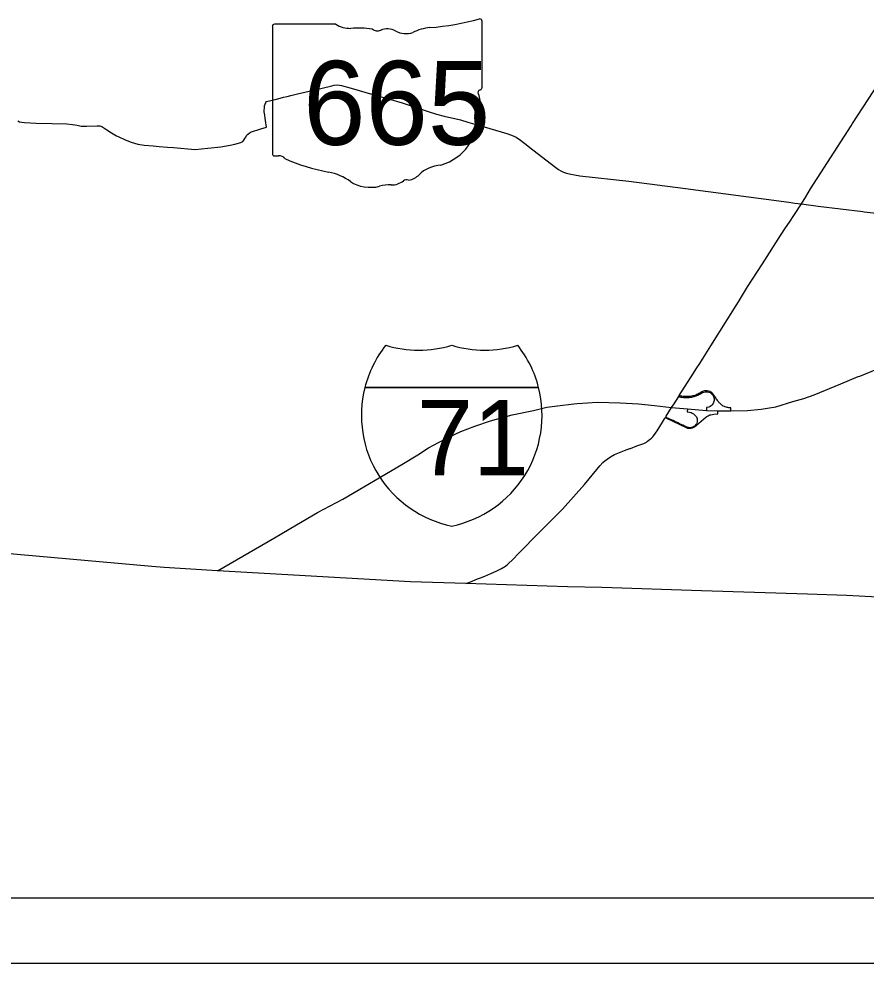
# Model space of a CAD drawing. Extents: x 0 to 34, y 0 to 22.
# Drawn here: x 2.835 to 4.137, y 14 to 15.45 of the extents above; entities that cross this region are included whole.
import ezdxf

# ---------------------------------------------------------------- set-up
doc = ezdxf.new("R2010")
doc.units = 0
for name, color, linetype in [('GM_X_County', 7, 'Continuous'), ('GM_X_Interchange_Ramps', 7, 'Continuous'), ('GM_X_Interstate_Route', 7, 'Continuous'), ('GM_X_Interstate_Shield', 7, 'Continuous'), ('GM_X_State_Route', 7, 'Continuous'), ('GM_X_State_Shield', 7, 'Continuous'), ('GM_X_US_Route', 7, 'Continuous'), ('SH_Data', 7, 'Continuous')]:
    doc.layers.add(name, color=color, linetype=linetype)

msp = doc.modelspace()

# ---------------------------------------------------------------- linework, layer by layer
at = {"layer": 'GM_X_County'}
msp.add_lwpolyline([(4.3469, 14.5519), (4.1065, 14.5646), (4.047, 14.5664), (3.8841, 14.5719), (3.731, 14.5769), (3.6781, 14.578), (3.5217, 14.5829), (3.4368, 14.5856), (3.1405, 14.6022), (3.0582, 14.6074), (3.0396, 14.6088), (2.5046, 14.6566)], dxfattribs=at)
at = {"layer": 'GM_X_Interchange_Ramps'}
for points in [[(3.849, 14.8703), (3.85, 14.8697), (3.8521, 14.8692), (3.8541, 14.869), (3.8561, 14.8688), (3.858, 14.8687), (3.8598, 14.8686), (3.8616, 14.8686), (3.8631, 14.8686), (3.865, 14.8687), (3.867, 14.8689), (3.8689, 14.8692), (3.8708, 14.8696), (3.8725, 14.87), (3.874, 14.8705), (3.8756, 14.871), (3.8769, 14.8715), (3.8784, 14.8722), (3.88, 14.8731), (3.8815, 14.8738), (3.883, 14.8746), (3.8857, 14.8761), (3.8874, 14.8769), (3.8896, 14.8774), (3.8914, 14.8775), (3.8933, 14.8773), (3.8952, 14.8769), (3.897, 14.8761), (3.8985, 14.8752), (3.8999, 14.8739), (3.9009, 14.8728), (3.9018, 14.8714), (3.9025, 14.87), (3.903, 14.8685), (3.9033, 14.867), (3.9035, 14.8655), (3.9034, 14.8639), (3.9031, 14.8625), (3.9026, 14.8609), (3.9019, 14.8595), (3.9015, 14.8587), (3.9005, 14.8575), (3.8997, 14.8566), (3.8987, 14.8557), (3.8974, 14.8549), (3.8964, 14.8544), (3.8953, 14.8539), (3.8918, 14.853), (3.8915, 14.8485)], [(3.929, 14.8479), (3.9291, 14.8525), (3.9259, 14.8528), (3.9246, 14.853), (3.9232, 14.8532), (3.9219, 14.8536), (3.9204, 14.8541), (3.9191, 14.8546), (3.9174, 14.8555), (3.9162, 14.8562), (3.9151, 14.8569), (3.914, 14.8577), (3.9129, 14.8587), (3.9119, 14.8597), (3.9113, 14.8603), (3.9106, 14.8612), (3.9096, 14.8626), (3.909, 14.8635), (3.9081, 14.8648), (3.9071, 14.8662), (3.9062, 14.8675), (3.9053, 14.8689), (3.9041, 14.8706), (3.9031, 14.872), (3.9022, 14.8733), (3.9009, 14.8749), (3.8996, 14.876), (3.8983, 14.8769), (3.8965, 14.8778), (3.8945, 14.8785), (3.8927, 14.8788), (3.8906, 14.8788), (3.8887, 14.8786), (3.887, 14.8782), (3.8857, 14.8776), (3.8846, 14.8771), (3.8828, 14.8761), (3.8813, 14.8753), (3.8798, 14.8745), (3.8784, 14.8738), (3.877, 14.873), (3.8754, 14.8724), (3.8738, 14.8718), (3.8719, 14.8713), (3.8705, 14.8709), (3.8685, 14.8705), (3.8664, 14.8702), (3.8644, 14.87), (3.8625, 14.87), (3.8607, 14.87), (3.859, 14.87), (3.8575, 14.8701), (3.8558, 14.8702), (3.8539, 14.8704), (3.8521, 14.8706), (3.8509, 14.8709), (3.8498, 14.8716)], [(3.8283, 14.838), (3.8304, 14.8367), (3.8602, 14.8225), (3.8625, 14.8217), (3.8646, 14.8213), (3.8664, 14.8213), (3.8682, 14.8215), (3.8699, 14.8219), (3.8711, 14.8223), (3.873, 14.8234), (3.876, 14.8259), (3.8906, 14.8382), (3.8922, 14.8395), (3.8941, 14.8406), (3.8956, 14.8413), (3.8967, 14.8417), (3.8984, 14.8422), (3.9009, 14.8427), (3.9031, 14.8429), (3.9091, 14.8433), (3.9091, 14.8479)], [(3.8623, 14.8514), (3.8619, 14.8468), (3.8657, 14.846), (3.8679, 14.8453), (3.8697, 14.8445), (3.8714, 14.8435), (3.8729, 14.8424), (3.8744, 14.8411), (3.8753, 14.84), (3.8761, 14.8389), (3.8768, 14.8373), (3.8772, 14.8357), (3.8774, 14.834), (3.8774, 14.8325), (3.8771, 14.831), (3.8766, 14.8294), (3.8761, 14.8282), (3.8753, 14.8269), (3.8744, 14.8258), (3.8733, 14.8248), (3.8719, 14.8238), (3.8703, 14.823), (3.8685, 14.8225), (3.8663, 14.8222), (3.8639, 14.8224), (3.8618, 14.8229), (3.8595, 14.8239), (3.8578, 14.8247), (3.8552, 14.8259), (3.8529, 14.827), (3.8502, 14.8283), (3.8475, 14.8296), (3.8454, 14.8306), (3.8432, 14.8317), (3.8403, 14.833), (3.8379, 14.8341), (3.8354, 14.8353), (3.8332, 14.8364), (3.8308, 14.8375), (3.8289, 14.8388)]]:
    msp.add_lwpolyline(points, dxfattribs=at)
at = {"layer": 'GM_X_Interstate_Route'}
for points in [[(4.1248, 14.9006), (4.1271, 14.9015), (4.1854, 14.9253), (4.2621, 14.9566), (4.3218, 14.9814), (4.379, 15.0051), (4.4021, 15.0166), (4.4136, 15.0232), (4.4186, 15.0266)], [(3.838, 14.8531), (3.8623, 14.8514), (3.8915, 14.8485), (3.9091, 14.8479), (3.929, 14.8479), (3.9546, 14.8485), (3.9754, 14.8508), (3.9979, 14.8544), (4.0244, 14.8622), (4.0411, 14.8671), (4.0568, 14.8728), (4.0978, 14.8893), (4.1248, 14.9006)], [(3.1405, 14.6022), (3.2278, 14.6531), (3.2617, 14.6728), (3.2938, 14.6919), (3.333, 14.7126), (3.4237, 14.7659), (3.448, 14.7806), (3.4644, 14.7911), (3.48, 14.7994), (3.4978, 14.8086), (3.5141, 14.8162), (3.5355, 14.8243), (3.5598, 14.8325), (3.5929, 14.8418), (3.626, 14.8486), (3.6462, 14.8535), (3.6627, 14.8559), (3.688, 14.8589), (3.693, 14.8593), (3.7088, 14.8605), (3.7238, 14.8612), (3.7592, 14.8606), (3.7871, 14.8588), (3.8119, 14.8563), (3.838, 14.8531)]]:
    msp.add_lwpolyline(points, dxfattribs=at)
at = {"layer": 'GM_X_Interstate_Shield'}
for p, q in [((3.3667, 14.8837), (3.6337, 14.8837)), ((3.6337, 14.8837), (3.3667, 14.8837)), ((3.6337, 14.8837), (3.3667, 14.8837))]:
    msp.add_line(p, q, dxfattribs=at)
for centre, start, end in [((3.5349, 14.8412), 141.669, 165.8066), ((3.4495, 15.1147), 253.0091, 286.9909), ((3.5509, 15.1147), 253.0091, 286.9909), ((3.4655, 14.8412), 14.1934, 38.331), ((3.5349, 14.8412), 165.8066, 258.463), ((3.4655, 14.8412), 281.537, 14.1934)]:
    msp.add_arc(centre, 0.1735, start, end, dxfattribs=at)
at = {"layer": 'GM_X_State_Route'}
for points in [[(3.0636, 15.253), (3.0729, 15.2523), (3.106, 15.2496), (3.1254, 15.2513), (3.1454, 15.2537), (3.16, 15.256), (3.1669, 15.2577), (3.1763, 15.2602), (3.1792, 15.2616), (3.181, 15.2635), (3.1825, 15.2661), (3.1837, 15.2683), (3.1851, 15.2708), (3.1864, 15.2723), (3.1883, 15.2738), (3.191, 15.2758), (3.2072, 15.281), (3.2158, 15.2839), (3.2141, 15.2939), (3.2124, 15.3053), (3.2123, 15.3064), (3.2127, 15.3163), (3.2146, 15.3218), (3.2154, 15.3231), (3.2312, 15.3269), (3.2365, 15.3283), (3.2419, 15.3296), (3.2474, 15.3308), (3.2529, 15.3321), (3.2635, 15.335), (3.2746, 15.3376), (3.2856, 15.34), (3.3013, 15.3438)], [(3.3013, 15.3438), (3.316, 15.3474), (3.3198, 15.3484), (3.3246, 15.3488), (3.328, 15.3483), (3.3309, 15.3477), (3.3456, 15.3435), (3.3791, 15.3341), (3.4033, 15.327)], [(3.4033, 15.327), (3.4243, 15.3209), (3.4471, 15.3135), (3.4658, 15.307), (3.477, 15.3036), (3.4888, 15.3005), (3.5138, 15.2947), (3.5249, 15.2916), (3.5503, 15.2841), (3.5851, 15.2739), (3.5922, 15.2714), (3.5957, 15.2698), (3.5992, 15.2681), (3.6027, 15.2659), (3.6052, 15.2641), (3.6085, 15.2618), (3.6123, 15.2586), (3.6248, 15.2488), (3.6599, 15.2218), (3.6642, 15.2189), (3.6678, 15.2167), (3.6718, 15.2148), (3.6764, 15.2132), (3.6832, 15.2115), (3.6887, 15.2103), (3.6972, 15.2091), (3.7722, 15.2006), (3.8596, 15.1894), (4.0179, 15.1683), (4.0272, 15.1671), (4.0373, 15.1659)], [(2.8337, 15.2932), (2.8364, 15.2921), (2.8396, 15.2913), (2.8439, 15.2909), (2.8618, 15.29), (2.886, 15.2892), (2.9091, 15.2887), (2.9174, 15.288), (2.9246, 15.2869), (2.9307, 15.2854), (2.9389, 15.2854), (2.9553, 15.2855), (2.9594, 15.2855), (2.961, 15.2853), (2.9626, 15.2848), (2.964, 15.2839), (2.9706, 15.2796), (2.9774, 15.275), (2.985, 15.2705), (2.9877, 15.2692)], [(2.9877, 15.2692), (2.9987, 15.2641), (3.0078, 15.2605), (3.0182, 15.2575), (3.0276, 15.2563), (3.0414, 15.2548), (3.0506, 15.2541), (3.0636, 15.253)], [(4.0373, 15.1659), (4.0631, 15.1626), (4.1317, 15.1541)], [(4.1317, 15.1541), (4.1339, 15.1538), (4.2478, 15.1407), (4.2727, 15.1378), (4.3329, 15.1306), (4.3973, 15.1229), (4.4585, 15.1153), (4.4659, 15.1145)]]:
    msp.add_lwpolyline(points, dxfattribs=at)
at = {"layer": 'GM_X_State_Shield'}
for p, q in [((3.5468, 15.3443), (3.5468, 15.4466)), ((3.2247, 15.4384), (3.2247, 15.2428)), ((3.3222, 15.4417), (3.2278, 15.4417)), ((3.5467, 15.3443), (3.5468, 15.3443))]:
    msp.add_line(p, q, dxfattribs=at)
for centre, major_axis, start_param, end_param in [((3.432, 15.7084), (0.3416, 0), 4.814394, 5.042369), ((3.5432, 15.447), (0.00359, 0), 6.141152, 7.989035), ((3.2283, 15.4388), (0.00373, 0), 1.712693, 3.28349), ((3.3446, 15.4644), (0.0362, 0), 4.042523, 4.731795), ((3.3566, 15.3319), (0.1299, 0), 1.404758, 1.657858), ((3.3861, 15.4398), (0.0104, 0), 3.836095, 5.185415), ((3.4015, 15.4172), (0.0217, 0), 0.950623, 2.079405), ((3.4295, 15.4482), (0.0261, 0), 4.081561, 5.145723), ((3.4756, 15.382), (0.0687, 0), 1.699011, 2.107814), ((3.5459, 15.3368), (0.00555, 0), 1.883978, 3.671073), ((3.5429, 15.3439), (0.00384, 0), 5.05454, 6.418171), ((3.5106, 15.3238), (0.0333, 0), 5.934695, 6.695948), ((3.5596, 15.3015), (0.0242, 0), 2.387724, 3.262537), ((3.4512, 15.2884), (0.0854, 0), 5.101752, 6.440018), ((3.2284, 15.2424), (0.00376, 0), 3.00124, 4.508301), ((3.2289, 15.2624), (0.0287, 0), 4.665946, 4.897461), ((3.2348, 15.2315), (0.0104, 0), 0.519207, 1.627899), ((3.3656, 15.4072), (0.2467, 0), 4.195997, 4.488961), ((3.4872, 15.1879), (0.0468, 0), 1.647645, 2.488434), ((3.2921, 15.1549), (0.0772, 0), 0.823519, 1.323587), ((3.4279, 15.2238), (0.0276, 0), 4.937069, 5.64225), ((3.3756, 15.2305), (0.049, 0), 4.026481, 4.996735), ((3.4074, 15.2159), (0.0261, 0), 4.691044, 5.507374), ((3.431, 15.1969), (0.00735, 0), 1.147584, 2.315152), ((3.4039, 15.1629), (0.0402, 0), 1.495662, 1.94098)]:
    msp.add_ellipse(centre, major_axis=major_axis, ratio=0.8, start_param=start_param, end_param=end_param, dxfattribs=at)
at = {"layer": 'GM_X_US_Route'}
for points in [[(4.1137, 15.2857), (4.1159, 15.2891), (4.1638, 15.363), (4.2009, 15.4215), (4.2142, 15.4425)], [(4.0373, 15.1659), (4.044, 15.1766), (4.0513, 15.1891), (4.1137, 15.2857)], [(3.9372, 15.0096), (3.941, 15.0156), (3.9546, 15.0383), (3.9776, 15.074), (4.0051, 15.1174), (4.0132, 15.129), (4.0193, 15.1377), (4.026, 15.1481), (4.0373, 15.1659)], [(3.8498, 14.8716), (3.8716, 14.906), (3.8759, 14.9124), (3.8812, 14.9208), (3.8908, 14.9358), (3.8983, 14.948), (3.9234, 14.9878), (3.9372, 15.0096)], [(3.8417, 14.8588), (3.849, 14.8703), (3.8498, 14.8716)], [(3.8269, 14.8357), (3.8283, 14.838), (3.8289, 14.8388), (3.8296, 14.84), (3.838, 14.8531), (3.8417, 14.8588)], [(3.7747, 14.7905), (3.7845, 14.7941), (3.7909, 14.7964), (3.7924, 14.7969), (3.7952, 14.798), (3.7972, 14.799), (3.7992, 14.8001), (3.8012, 14.8014), (3.8031, 14.8028), (3.8058, 14.8049), (3.8073, 14.8062), (3.8092, 14.8082), (3.8107, 14.8103), (3.8156, 14.8174), (3.8238, 14.8309), (3.8269, 14.8357)], [(3.5792, 14.6074), (3.5811, 14.6086), (3.5853, 14.6118), (3.5957, 14.6212), (3.6012, 14.6277), (3.6362, 14.6627), (3.6704, 14.697), (3.7043, 14.735), (3.7232, 14.758), (3.7279, 14.7638), (3.7324, 14.7687), (3.7356, 14.7713), (3.7388, 14.7738), (3.7441, 14.7775), (3.7501, 14.7808), (3.7556, 14.7832), (3.7604, 14.785), (3.7655, 14.787), (3.7737, 14.7901), (3.7747, 14.7905)], [(3.5443, 14.5917), (3.5509, 14.5942), (3.5601, 14.5984), (3.5685, 14.6019), (3.5768, 14.6058), (3.5792, 14.6074)], [(3.5217, 14.5829), (3.5278, 14.5851), (3.5398, 14.59), (3.5443, 14.5917)]]:
    msp.add_lwpolyline(points, dxfattribs=at)
at = {"layer": 'SH_Data'}
for p, q in [((2.1, 14.1), (8.9, 14.1)), ((2, 14), (9, 14))]:
    msp.add_line(p, q, dxfattribs=at)

# ---------------------------------------------------------------- texts
at = {"layer": 'GM_X_Interstate_Shield'}
msp.add_text('71', height=0.11569, dxfattribs=at).set_placement((3.4468, 14.7492))
at = {"layer": 'GM_X_State_Shield'}
msp.add_text('665', height=0.12885, dxfattribs=at).set_placement((3.2719, 15.2566))

doc.saveas('drawing.dxf')
